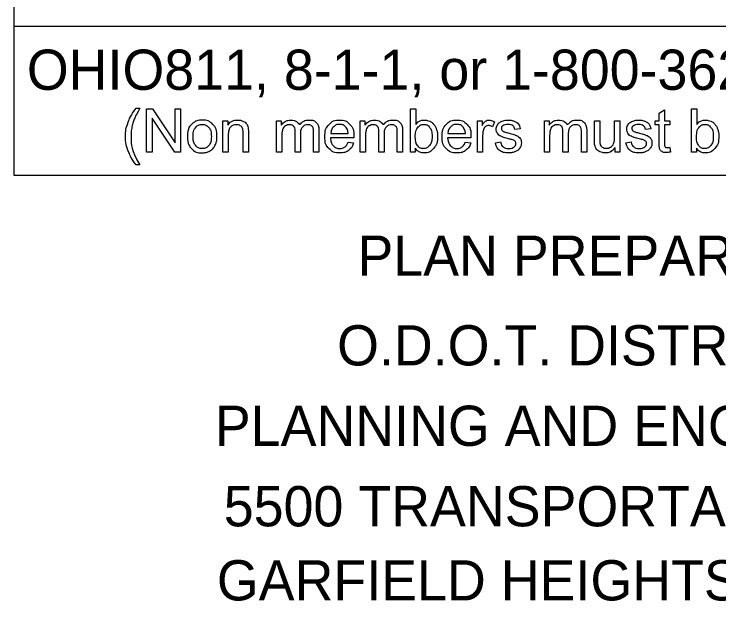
# Model space of a CAD drawing. Extents: x -59 to 82, y -3 to 49.
# Drawn here: x -54.02 to -51.567, y 29.029 to 31.095 of the extents above; entities that cross this region are included whole.
import ezdxf

# ---------------------------------------------------------------- set-up
doc = ezdxf.new("R2010")
doc.units = 0
doc.layers.add('SH_Data', color=7, linetype='Continuous')
doc.layers.add('SH_Text', color=7, linetype='Continuous')

msp = doc.modelspace()

# ---------------------------------------------------------------- linework, layer by layer
at = {"layer": 'SH_Data'}
for p, q in [((-54.0205, 30.534), (-54.0205, 32.8715)), ((-49.7705, 31.0519), (-54.0205, 31.0519)), ((-49.7705, 30.534), (-54.0205, 30.534))]:
    msp.add_line(p, q, dxfattribs=at)
at = {"layer": 'SH_Text'}
for points in [[(-53.5959, 30.7678), (-53.5827, 30.7678)], [(-53.5591, 30.6152), (-53.5591, 30.7653), (-53.5388, 30.7653), (-53.4598, 30.6474), (-53.4598, 30.7653), (-53.4408, 30.7653), (-53.4408, 30.6152), (-53.4611, 30.6152), (-53.5401, 30.7331), (-53.5401, 30.6152), (-53.5591, 30.6152)], [(-52.6237, 30.6152), (-52.6407, 30.6152), (-52.6407, 30.7653), (-52.6223, 30.7653), (-52.6223, 30.7118)], [(-51.7747, 30.647), (-51.7747, 30.7097), (-51.7883, 30.7097), (-51.7883, 30.724), (-51.7747, 30.724), (-51.7747, 30.7509), (-51.7563, 30.762), (-51.7563, 30.724), (-51.7379, 30.724), (-51.7379, 30.7097), (-51.7563, 30.7097), (-51.7563, 30.6459)], [(-51.6446, 30.6152), (-51.6616, 30.6152), (-51.6616, 30.7653), (-51.6432, 30.7653), (-51.6432, 30.7118)], [(-53.2932, 30.6152), (-53.2932, 30.724), (-53.2766, 30.724), (-53.2766, 30.7085)], [(-53.1067, 30.6152), (-53.1067, 30.724), (-53.0903, 30.724), (-53.0903, 30.7086)], [(-52.8154, 30.6152), (-52.8154, 30.724), (-52.7989, 30.724), (-52.7989, 30.7086)], [(-52.4076, 30.6152), (-52.4076, 30.724), (-52.391, 30.724), (-52.391, 30.7075)], [(-52.1744, 30.6152), (-52.1744, 30.724), (-52.1579, 30.724), (-52.1579, 30.7086)], [(-52.0001, 30.6566), (-52.0001, 30.724), (-51.9816, 30.724), (-51.9816, 30.6637)], [(-51.9304, 30.6657), (-51.9304, 30.724), (-51.9119, 30.724), (-51.9119, 30.6152), (-51.9284, 30.6152)], [(-52.3485, 30.7205), (-52.355, 30.7035)], [(-53.2747, 30.6746), (-53.2747, 30.6152), (-53.2932, 30.6152)], [(-53.2048, 30.6821), (-53.2048, 30.6152), (-53.2232, 30.6152), (-53.2232, 30.6813)], [(-53.0237, 30.6783), (-53.0237, 30.6152), (-53.0421, 30.6152), (-53.0421, 30.6858)], [(-52.9592, 30.6898), (-52.9592, 30.6152), (-52.9777, 30.6152), (-52.9777, 30.6837)], [(-52.9181, 30.6799), (-52.8574, 30.6799)], [(-52.7323, 30.6783), (-52.7323, 30.6152), (-52.7507, 30.6152), (-52.7507, 30.6858)], [(-52.6679, 30.6898), (-52.6679, 30.6152), (-52.6863, 30.6152), (-52.6863, 30.6837)], [(-52.5101, 30.6799), (-52.4494, 30.6799)], [(-52.3892, 30.6722), (-52.3892, 30.6152), (-52.4076, 30.6152)], [(-52.2586, 30.6959), (-52.2767, 30.6935)], [(-52.0913, 30.6783), (-52.0913, 30.6152), (-52.1097, 30.6152), (-52.1097, 30.6858)], [(-52.0269, 30.6898), (-52.0269, 30.6152), (-52.0453, 30.6152), (-52.0453, 30.6837)], [(-51.804, 30.6959), (-51.8221, 30.6935)], [(-53.0883, 30.6716), (-53.0883, 30.6152), (-53.1067, 30.6152)], [(-52.838, 30.6648), (-52.9192, 30.6648)], [(-52.8576, 30.6503), (-52.8385, 30.6479)], [(-52.7969, 30.6716), (-52.7969, 30.6152), (-52.8154, 30.6152)], [(-52.43, 30.6648), (-52.5112, 30.6648)], [(-52.4496, 30.6503), (-52.4305, 30.6479)], [(-52.345, 30.6477), (-52.3268, 30.6505)], [(-52.156, 30.6716), (-52.156, 30.6152), (-52.1744, 30.6152)], [(-51.8904, 30.6477), (-51.8722, 30.6505)], [(-52.6237, 30.6288), (-52.6237, 30.6152)], [(-51.9284, 30.6152), (-51.9284, 30.6312)], [(-51.7379, 30.6316), (-51.7352, 30.6153)], [(-51.6446, 30.6288), (-51.6446, 30.6152)], [(-53.5827, 30.571), (-53.5959, 30.571)]]:
    msp.add_lwpolyline(points, dxfattribs=at)
for points in [[(-53.5959, 30.571), (-53.6111, 30.5902), (-53.6217, 30.6161), (-53.6323, 30.6419), (-53.6323, 30.6695), (-53.6323, 30.6939), (-53.6244, 30.7162), (-53.6151, 30.7421), (-53.5959, 30.7678)], [(-53.5827, 30.7678), (-53.5951, 30.7465), (-53.599, 30.7374), (-53.6053, 30.7233), (-53.6089, 30.7079), (-53.6133, 30.6888), (-53.6133, 30.6694), (-53.6133, 30.6202), (-53.5827, 30.571)], [(-53.4166, 30.6696), (-53.4166, 30.6998), (-53.3999, 30.7143), (-53.3858, 30.7264), (-53.3657, 30.7264), (-53.3432, 30.7264), (-53.329, 30.7117), (-53.3148, 30.697), (-53.3148, 30.6711), (-53.3148, 30.6501), (-53.3211, 30.6381), (-53.3274, 30.6261), (-53.3394, 30.6194), (-53.3514, 30.6128), (-53.3657, 30.6128), (-53.3885, 30.6128), (-53.4026, 30.6274), (-53.4166, 30.642), (-53.4166, 30.6696)], [(-53.2766, 30.7085), (-53.2646, 30.7264), (-53.242, 30.7264), (-53.2321, 30.7264), (-53.2239, 30.7229), (-53.2157, 30.7193), (-53.2116, 30.7136), (-53.2075, 30.7079), (-53.2058, 30.7), (-53.2048, 30.6949), (-53.2048, 30.6821)], [(-53.0903, 30.7086), (-53.0851, 30.7167), (-53.0766, 30.7215), (-53.0681, 30.7264), (-53.0573, 30.7264), (-53.0452, 30.7264), (-53.0374, 30.7214), (-53.0297, 30.7163), (-53.0265, 30.7073), (-53.0136, 30.7264), (-52.9929, 30.7264), (-52.9767, 30.7264), (-52.9679, 30.7174), (-52.9592, 30.7085), (-52.9592, 30.6898)], [(-52.8385, 30.6479), (-52.843, 30.6312), (-52.8552, 30.622), (-52.8674, 30.6128), (-52.8863, 30.6128), (-52.9102, 30.6128), (-52.9242, 30.6275), (-52.9382, 30.6422), (-52.9382, 30.6687), (-52.9382, 30.6961), (-52.924, 30.7113), (-52.9099, 30.7264), (-52.8874, 30.7264), (-52.8655, 30.7264), (-52.8517, 30.7116), (-52.8379, 30.6967), (-52.8379, 30.6698), (-52.8379, 30.6681), (-52.838, 30.6648)], [(-52.7989, 30.7086), (-52.7938, 30.7167), (-52.7853, 30.7215), (-52.7768, 30.7264), (-52.7659, 30.7264), (-52.7538, 30.7264), (-52.7461, 30.7214), (-52.7383, 30.7163), (-52.7352, 30.7073), (-52.7222, 30.7264), (-52.7015, 30.7264), (-52.6853, 30.7264), (-52.6766, 30.7174), (-52.6679, 30.7085), (-52.6679, 30.6898)], [(-52.6223, 30.7118), (-52.6106, 30.7264), (-52.5925, 30.7264), (-52.5825, 30.7264), (-52.5735, 30.7224), (-52.5645, 30.7183), (-52.5588, 30.711), (-52.553, 30.7037), (-52.5497, 30.6933), (-52.5464, 30.683), (-52.5464, 30.6712), (-52.5464, 30.6433), (-52.5602, 30.628), (-52.5741, 30.6128), (-52.5934, 30.6128), (-52.6127, 30.6128), (-52.6237, 30.6288)], [(-52.4305, 30.6479), (-52.435, 30.6312), (-52.4472, 30.622), (-52.4594, 30.6128), (-52.4783, 30.6128), (-52.5022, 30.6128), (-52.5162, 30.6275), (-52.5302, 30.6422), (-52.5302, 30.6687), (-52.5302, 30.6961), (-52.516, 30.7113), (-52.5019, 30.7264), (-52.4794, 30.7264), (-52.4576, 30.7264), (-52.4437, 30.7116), (-52.4299, 30.6967), (-52.4299, 30.6698), (-52.4299, 30.6681), (-52.43, 30.6648)], [(-52.391, 30.7075), (-52.3847, 30.7191), (-52.3793, 30.7227), (-52.3739, 30.7264), (-52.3675, 30.7264), (-52.3582, 30.7264), (-52.3485, 30.7205)], [(-52.3268, 30.6505), (-52.3253, 30.6396), (-52.3182, 30.6337), (-52.3112, 30.6279), (-52.2985, 30.6279), (-52.2858, 30.6279), (-52.2796, 30.6331), (-52.2735, 30.6382), (-52.2735, 30.6452), (-52.2735, 30.6515), (-52.2789, 30.6551), (-52.2827, 30.6575), (-52.2978, 30.6613), (-52.3181, 30.6664), (-52.3259, 30.6702), (-52.3338, 30.6739), (-52.3378, 30.6805), (-52.3419, 30.6871), (-52.3419, 30.6951), (-52.3419, 30.7024), (-52.3386, 30.7086), (-52.3352, 30.7147), (-52.3295, 30.7188), (-52.3252, 30.722), (-52.3177, 30.7242), (-52.3103, 30.7264), (-52.3018, 30.7264), (-52.289, 30.7264), (-52.2793, 30.7227), (-52.2696, 30.719), (-52.2649, 30.7127), (-52.2603, 30.7064), (-52.2586, 30.6959)], [(-52.1579, 30.7086), (-52.1528, 30.7167), (-52.1443, 30.7215), (-52.1358, 30.7264), (-52.1249, 30.7264), (-52.1128, 30.7264), (-52.1051, 30.7214), (-52.0973, 30.7163), (-52.0942, 30.7073), (-52.0812, 30.7264), (-52.0605, 30.7264), (-52.0443, 30.7264), (-52.0356, 30.7174), (-52.0269, 30.7085), (-52.0269, 30.6898)], [(-51.8722, 30.6505), (-51.8707, 30.6396), (-51.8636, 30.6337), (-51.8566, 30.6279), (-51.844, 30.6279), (-51.8312, 30.6279), (-51.8251, 30.6331), (-51.8189, 30.6382), (-51.8189, 30.6452), (-51.8189, 30.6515), (-51.8243, 30.6551), (-51.8281, 30.6575), (-51.8432, 30.6613), (-51.8635, 30.6664), (-51.8714, 30.6702), (-51.8792, 30.6739), (-51.8833, 30.6805), (-51.8873, 30.6871), (-51.8873, 30.6951), (-51.8873, 30.7024), (-51.884, 30.7086), (-51.8807, 30.7147), (-51.8749, 30.7188), (-51.8706, 30.722), (-51.8632, 30.7242), (-51.8557, 30.7264), (-51.8472, 30.7264), (-51.8344, 30.7264), (-51.8247, 30.7227), (-51.815, 30.719), (-51.8104, 30.7127), (-51.8058, 30.7064), (-51.804, 30.6959)], [(-51.6432, 30.7118), (-51.6315, 30.7264), (-51.6134, 30.7264), (-51.6034, 30.7264), (-51.5944, 30.7224), (-51.5855, 30.7183), (-51.5797, 30.711), (-51.5739, 30.7037), (-51.5706, 30.6933), (-51.5673, 30.683), (-51.5673, 30.6712), (-51.5673, 30.6433), (-51.5812, 30.628), (-51.595, 30.6128), (-51.6144, 30.6128), (-51.6336, 30.6128), (-51.6446, 30.6288)], [(-53.3976, 30.6696), (-53.3976, 30.6487), (-53.3885, 30.6383), (-53.3795, 30.6279), (-53.3657, 30.6279), (-53.352, 30.6279), (-53.3429, 30.6383), (-53.3338, 30.6488), (-53.3338, 30.6702), (-53.3338, 30.6904), (-53.3429, 30.7008), (-53.3521, 30.7112), (-53.3657, 30.7112), (-53.3795, 30.7112), (-53.3885, 30.7008), (-53.3976, 30.6905), (-53.3976, 30.6696)], [(-53.2232, 30.6813), (-53.2232, 30.6926), (-53.2254, 30.6982), (-53.2275, 30.7037), (-53.233, 30.7071), (-53.2385, 30.7104), (-53.2459, 30.7104), (-53.2576, 30.7104), (-53.2662, 30.7029), (-53.2747, 30.6954), (-53.2747, 30.6746)], [(-53.0421, 30.6858), (-53.0421, 30.6981), (-53.0466, 30.7042), (-53.0511, 30.7104), (-53.0614, 30.7104), (-53.0692, 30.7104), (-53.0758, 30.7063), (-53.0824, 30.7022), (-53.0853, 30.6943), (-53.0883, 30.6864), (-53.0883, 30.6716)], [(-52.9777, 30.6837), (-52.9777, 30.6947), (-52.9794, 30.6996), (-52.9812, 30.7044), (-52.986, 30.7074), (-52.9907, 30.7104), (-52.997, 30.7104), (-53.0085, 30.7104), (-53.0161, 30.7028), (-53.0237, 30.6951), (-53.0237, 30.6783)], [(-52.8574, 30.6799), (-52.8586, 30.6937), (-52.8643, 30.7006), (-52.8731, 30.7113), (-52.8872, 30.7113), (-52.8999, 30.7113), (-52.9085, 30.7028), (-52.9172, 30.6942), (-52.9181, 30.6799)], [(-52.7507, 30.6858), (-52.7507, 30.6981), (-52.7552, 30.7042), (-52.7597, 30.7104), (-52.77, 30.7104), (-52.7778, 30.7104), (-52.7844, 30.7063), (-52.791, 30.7022), (-52.794, 30.6943), (-52.7969, 30.6864), (-52.7969, 30.6716)], [(-52.6863, 30.6837), (-52.6863, 30.6947), (-52.6881, 30.6996), (-52.6899, 30.7044), (-52.6946, 30.7074), (-52.6993, 30.7104), (-52.7056, 30.7104), (-52.7171, 30.7104), (-52.7247, 30.7028), (-52.7323, 30.6951), (-52.7323, 30.6783)], [(-52.6239, 30.6704), (-52.6239, 30.6508), (-52.6186, 30.6421), (-52.6099, 30.6279), (-52.5951, 30.6279), (-52.583, 30.6279), (-52.5742, 30.6384), (-52.5654, 30.6489), (-52.5654, 30.6697), (-52.5654, 30.691), (-52.5738, 30.7012), (-52.5823, 30.7113), (-52.5942, 30.7113), (-52.6063, 30.7113), (-52.6151, 30.7008), (-52.6239, 30.6903), (-52.6239, 30.6704)], [(-52.4494, 30.6799), (-52.4506, 30.6937), (-52.4563, 30.7006), (-52.4651, 30.7113), (-52.4792, 30.7113), (-52.4919, 30.7113), (-52.5006, 30.7028), (-52.5092, 30.6942), (-52.5101, 30.6799)], [(-52.355, 30.7035), (-52.3617, 30.7074), (-52.3685, 30.7074), (-52.3745, 30.7074), (-52.3793, 30.7038), (-52.384, 30.7001), (-52.3861, 30.6937), (-52.3892, 30.6838), (-52.3892, 30.6722)], [(-52.2767, 30.6935), (-52.2779, 30.7019), (-52.2838, 30.7066), (-52.2897, 30.7113), (-52.3005, 30.7113), (-52.3132, 30.7113), (-52.3186, 30.7071), (-52.324, 30.7029), (-52.324, 30.6972), (-52.324, 30.6937), (-52.3218, 30.6908), (-52.3195, 30.6878), (-52.3147, 30.6859), (-52.3119, 30.6848), (-52.2984, 30.6811), (-52.2788, 30.6759), (-52.2711, 30.6726), (-52.2633, 30.6693), (-52.2589, 30.6629), (-52.2545, 30.6566), (-52.2545, 30.6472), (-52.2545, 30.6379), (-52.2599, 30.6298), (-52.2652, 30.6217), (-52.2754, 30.6172), (-52.2856, 30.6128), (-52.2984, 30.6128), (-52.3196, 30.6128), (-52.3308, 30.6216), (-52.3419, 30.6304), (-52.345, 30.6477)], [(-52.1097, 30.6858), (-52.1097, 30.6981), (-52.1142, 30.7042), (-52.1187, 30.7104), (-52.129, 30.7104), (-52.1368, 30.7104), (-52.1434, 30.7063), (-52.15, 30.7022), (-52.153, 30.6943), (-52.156, 30.6864), (-52.156, 30.6716)], [(-52.0453, 30.6837), (-52.0453, 30.6947), (-52.0471, 30.6996), (-52.0489, 30.7044), (-52.0536, 30.7074), (-52.0583, 30.7104), (-52.0646, 30.7104), (-52.0761, 30.7104), (-52.0837, 30.7028), (-52.0913, 30.6951), (-52.0913, 30.6783)], [(-51.8221, 30.6935), (-51.8233, 30.7019), (-51.8292, 30.7066), (-51.8351, 30.7113), (-51.8459, 30.7113), (-51.8586, 30.7113), (-51.864, 30.7071), (-51.8695, 30.7029), (-51.8695, 30.6972), (-51.8695, 30.6937), (-51.8672, 30.6908), (-51.865, 30.6878), (-51.8601, 30.6859), (-51.8574, 30.6848), (-51.8438, 30.6811), (-51.8243, 30.6759), (-51.8165, 30.6726), (-51.8087, 30.6693), (-51.8043, 30.6629), (-51.7999, 30.6566), (-51.7999, 30.6472), (-51.7999, 30.6379), (-51.8053, 30.6298), (-51.8107, 30.6217), (-51.8208, 30.6172), (-51.831, 30.6128), (-51.8438, 30.6128), (-51.8651, 30.6128), (-51.8762, 30.6216), (-51.8873, 30.6304), (-51.8904, 30.6477)], [(-51.6448, 30.6704), (-51.6448, 30.6508), (-51.6395, 30.6421), (-51.6308, 30.6279), (-51.616, 30.6279), (-51.6039, 30.6279), (-51.5951, 30.6384), (-51.5863, 30.6489), (-51.5863, 30.6697), (-51.5863, 30.691), (-51.5948, 30.7012), (-51.6032, 30.7113), (-51.6152, 30.7113), (-51.6272, 30.7113), (-51.636, 30.7008), (-51.6448, 30.6903), (-51.6448, 30.6704)], [(-52.9192, 30.6648), (-52.9181, 30.6469), (-52.909, 30.6374), (-52.8999, 30.6279), (-52.8863, 30.6279), (-52.8761, 30.6279), (-52.8689, 30.6332), (-52.8618, 30.6386), (-52.8576, 30.6503)], [(-52.5112, 30.6648), (-52.5101, 30.6469), (-52.501, 30.6374), (-52.4919, 30.6279), (-52.4783, 30.6279), (-52.4681, 30.6279), (-52.4609, 30.6332), (-52.4538, 30.6386), (-52.4496, 30.6503)], [(-51.9284, 30.6312), (-51.9411, 30.6128), (-51.9629, 30.6128), (-51.9725, 30.6128), (-51.9809, 30.6165), (-51.9892, 30.6201), (-51.9933, 30.6257), (-51.9973, 30.6313), (-51.9989, 30.6394), (-52.0001, 30.6448), (-52.0001, 30.6566)], [(-51.9816, 30.6637), (-51.9816, 30.6493), (-51.9805, 30.6442), (-51.9788, 30.637), (-51.9731, 30.6328), (-51.9675, 30.6287), (-51.9592, 30.6287), (-51.9509, 30.6287), (-51.9437, 30.6329), (-51.9364, 30.6372), (-51.9334, 30.6445), (-51.9304, 30.6518), (-51.9304, 30.6657)], [(-51.7352, 30.6153), (-51.743, 30.6137), (-51.7491, 30.6137), (-51.7592, 30.6137), (-51.7647, 30.6169), (-51.7702, 30.62), (-51.7725, 30.6252), (-51.7747, 30.6304), (-51.7747, 30.647)], [(-51.7563, 30.6459), (-51.7563, 30.638), (-51.7553, 30.6358), (-51.7544, 30.6335), (-51.7522, 30.6322), (-51.75, 30.6308), (-51.7459, 30.6308), (-51.7429, 30.6308), (-51.7379, 30.6316)]]:
    msp.add_open_spline(points, degree=3, dxfattribs=at)

# ---------------------------------------------------------------- texts
for s, p in [('OHIO811, 8-1-1, or 1-800-362-2764', (-53.976, 30.8319)), ('PLAN PREPARED BY:', (-52.8252, 30.1846)), ('O.D.O.T. DISTRICT 12', (-52.8959, 29.8726)), ('PLANNING AND ENGINEERING', (-53.3216, 29.5926)), ('5500 TRANSPORTATION BLVD.', (-53.2906, 29.3126)), ('GARFIELD HEIGHTS, OH 44125', (-53.3145, 29.0547))]:
    msp.add_text(s, height=0.14, dxfattribs=at).set_placement(p)

doc.saveas('drawing.dxf')
